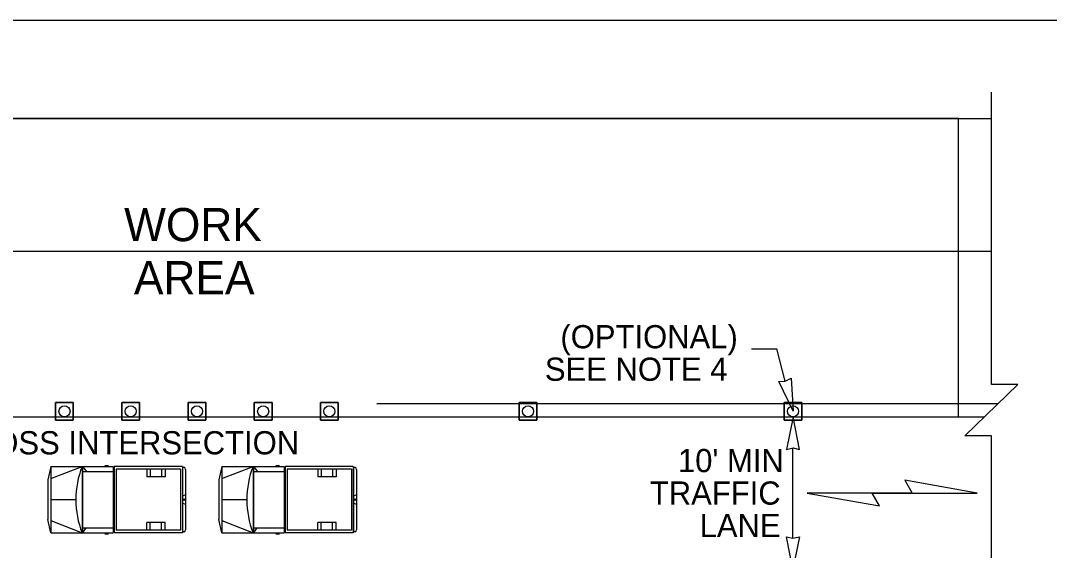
# Model space of a CAD drawing. Extents: x 99999.1 to 100095.7, y 99995 to 100010.7.
# Drawn here: x 100062.093 to 100065.2, y 100004.382 to 100005.98 of the extents above; entities that cross this region are included whole.
import ezdxf

# ---------------------------------------------------------------- set-up
doc = ezdxf.new("R2010")
doc.units = 0
for name, color, linetype in [('RD_ED_ShoulderPavedEdge', 7, 'Continuous'), ('RD_MK_LineDblYellowCenter', 7, 'Continuous'), ('RD_MK_LineEdgeWhite', 7, 'Continuous'), ('TR_WZ_MotoristVehicle', 7, 'Continuous'), ('TR_WZ_TrafficCone', 7, 'Continuous'), ('TR_WZ_WorkAreaLabel', 7, 'Continuous'), ('TR_WZ_WorkZoneDetails', 7, 'Continuous'), ('TR_WZ_WorkZoneTextCurrent', 7, 'Continuous')]:
    doc.layers.add(name, color=color, linetype=linetype)

msp = doc.modelspace()

# ---------------------------------------------------------------- linework, layer by layer
at = {"layer": 'RD_ED_ShoulderPavedEdge'}
msp.add_line((100060.225, 100005.6849), (100065.025, 100005.6849), dxfattribs=at)
at = {"layer": 'RD_MK_LineDblYellowCenter'}
for p, q in [((100063.1688, 100004.8249), (100065.0457, 100004.8249)), ((100063.1688, 100004.7849), (100065.0043, 100004.7849))]:
    msp.add_line(p, q, dxfattribs=at)
at = {"layer": 'RD_MK_LineEdgeWhite'}
msp.add_line((100060.225, 100005.2849), (100065.025, 100005.2849), dxfattribs=at)
at = {"layer": 'TR_WZ_MotoristVehicle'}
for p, q in [((100062.1843, 100004.6349), (100062.175, 100004.5946)), ((100062.1843, 100004.6349), (100062.1843, 100004.4349)), ((100062.1843, 100004.6349), (100062.3732, 100004.6349)), ((100062.1843, 100004.5983), (100062.2787, 100004.6349)), ((100062.2787, 100004.6349), (100062.2787, 100004.4349)), ((100062.2804, 100004.6349), (100062.2804, 100004.4349)), ((100062.2804, 100004.6349), (100062.2925, 100004.6194)), ((100062.3474, 100004.6377), (100062.3587, 100004.6377)), ((100062.3732, 100004.6349), (100062.3732, 100004.4349)), ((100062.5816, 100004.6349), (100062.3759, 100004.6349)), ((100062.3759, 100004.6349), (100062.3759, 100004.4349)), ((100062.5816, 100004.6349), (100062.5816, 100004.4349)), ((100062.5868, 100004.6316), (100062.5823, 100004.6316)), ((100062.5823, 100004.6316), (100062.5823, 100004.4382)), ((100062.7005, 100004.6349), (100062.6913, 100004.5946)), ((100062.7005, 100004.6349), (100062.7005, 100004.4349)), ((100062.7005, 100004.6349), (100062.8894, 100004.6349)), ((100062.7005, 100004.5983), (100062.795, 100004.6349)), ((100062.795, 100004.6349), (100062.795, 100004.4349)), ((100062.7967, 100004.6349), (100062.7967, 100004.4349)), ((100062.7967, 100004.6349), (100062.8087, 100004.6194)), ((100062.8637, 100004.6377), (100062.875, 100004.6377)), ((100062.8894, 100004.6349), (100062.8894, 100004.4349)), ((100063.0979, 100004.6349), (100062.8922, 100004.6349)), ((100062.8922, 100004.6349), (100062.8922, 100004.4349)), ((100063.0979, 100004.6349), (100063.0979, 100004.4349)), ((100063.1031, 100004.6316), (100063.0986, 100004.6316)), ((100063.0986, 100004.6316), (100063.0986, 100004.4382)), ((100062.2804, 100004.6194), (100062.3732, 100004.6194)), ((100062.5758, 100004.6269), (100062.3818, 100004.6269)), ((100062.3818, 100004.6269), (100062.3818, 100004.4429)), ((100062.4745, 100004.6269), (100062.4745, 100004.6039)), ((100062.5294, 100004.6039), (100062.4745, 100004.6039)), ((100062.4844, 100004.6269), (100062.4844, 100004.6039)), ((100062.5185, 100004.6269), (100062.5185, 100004.6039)), ((100062.5294, 100004.6269), (100062.5294, 100004.6039)), ((100062.5758, 100004.6269), (100062.5758, 100004.4429)), ((100062.5913, 100004.6255), (100062.5913, 100004.4443)), ((100062.7967, 100004.6194), (100062.8894, 100004.6194)), ((100063.0921, 100004.6269), (100062.898, 100004.6269)), ((100062.898, 100004.6269), (100062.898, 100004.4429)), ((100062.9908, 100004.6269), (100062.9908, 100004.6039)), ((100063.0457, 100004.6039), (100062.9908, 100004.6039)), ((100063.0007, 100004.6269), (100063.0007, 100004.6039)), ((100063.0347, 100004.6269), (100063.0347, 100004.6039)), ((100063.0457, 100004.6269), (100063.0457, 100004.6039)), ((100063.0921, 100004.6269), (100063.0921, 100004.4429)), ((100063.1075, 100004.6255), (100063.1075, 100004.4443)), ((100062.175, 100004.5946), (100062.175, 100004.4753)), ((100062.6913, 100004.5946), (100062.6913, 100004.4753)), ((100062.1843, 100004.5349), (100062.2602, 100004.5349)), ((100062.5913, 100004.549), (100062.5823, 100004.5453)), ((100062.5889, 100004.5349), (100062.5847, 100004.5349)), ((100062.5868, 100004.5377), (100062.5868, 100004.5321)), ((100062.7005, 100004.5349), (100062.7764, 100004.5349)), ((100063.1075, 100004.549), (100063.0986, 100004.5453)), ((100063.1051, 100004.5349), (100063.101, 100004.5349)), ((100063.1031, 100004.5377), (100063.1031, 100004.5321)), ((100062.5913, 100004.5208), (100062.5823, 100004.5246)), ((100063.1075, 100004.5208), (100063.0986, 100004.5246)), ((100062.1843, 100004.4349), (100062.175, 100004.4753)), ((100062.7005, 100004.4349), (100062.6913, 100004.4753)), ((100062.1843, 100004.4716), (100062.2787, 100004.4349)), ((100062.2804, 100004.4504), (100062.3732, 100004.4504)), ((100062.2904, 100004.4504), (100062.2804, 100004.4349)), ((100062.5758, 100004.4429), (100062.3818, 100004.4429)), ((100062.4745, 100004.4429), (100062.4745, 100004.4659)), ((100062.5294, 100004.4659), (100062.4745, 100004.4659)), ((100062.4844, 100004.4429), (100062.4844, 100004.4659)), ((100062.5185, 100004.4429), (100062.5185, 100004.4659)), ((100062.5294, 100004.4429), (100062.5294, 100004.4659)), ((100062.7005, 100004.4716), (100062.795, 100004.4349)), ((100062.7967, 100004.4504), (100062.8894, 100004.4504)), ((100062.8067, 100004.4504), (100062.7967, 100004.4349)), ((100063.0921, 100004.4429), (100062.898, 100004.4429)), ((100062.9908, 100004.4429), (100062.9908, 100004.4659)), ((100063.0457, 100004.4659), (100062.9908, 100004.4659)), ((100063.0007, 100004.4429), (100063.0007, 100004.4659)), ((100063.0347, 100004.4429), (100063.0347, 100004.4659)), ((100063.0457, 100004.4429), (100063.0457, 100004.4659)), ((100062.1843, 100004.4349), (100062.3732, 100004.4349)), ((100062.3474, 100004.4321), (100062.3587, 100004.4321)), ((100062.5816, 100004.4349), (100062.3759, 100004.4349)), ((100062.5868, 100004.4382), (100062.5823, 100004.4382)), ((100062.7005, 100004.4349), (100062.8894, 100004.4349)), ((100062.8637, 100004.4321), (100062.875, 100004.4321)), ((100063.0979, 100004.4349), (100062.8922, 100004.4349)), ((100063.1031, 100004.4382), (100063.0986, 100004.4382))]:
    msp.add_line(p, q, dxfattribs=at)
for centre, major_axis, start_param, end_param in [((100062.4137, 100004.5349), (0, -0.2099), 4.215667, 5.208926), ((100062.5868, 100004.6255), (0, 0.0061), 4.712389, 6.283185), ((100062.93, 100004.5349), (0, -0.2099), 4.215667, 5.208926), ((100063.1031, 100004.6255), (0, 0.0061), 4.712389, 6.283185), ((100062.5868, 100004.4443), (0, -0.0061), 0, 1.570796), ((100063.1031, 100004.4443), (0, -0.0061), 0, 1.570796)]:
    msp.add_ellipse(centre, major_axis=major_axis, ratio=0.73155, start_param=start_param, end_param=end_param, dxfattribs=at)
for centre in [(100062.5868, 100004.5349), (100063.1031, 100004.5349)]:
    msp.add_ellipse(centre, major_axis=(0, 0.00282), ratio=0.73155, dxfattribs=at)
at = {"layer": 'TR_WZ_TrafficCone'}
for points in [[(100062.199, 100004.8283), (100062.2524, 100004.8283), (100062.2524, 100004.7749), (100062.199, 100004.7749), (100062.199, 100004.8283)], [(100062.199, 100004.7749), (100062.2524, 100004.7749), (100062.2524, 100004.8283), (100062.199, 100004.8283), (100062.199, 100004.7749)], [(100062.399, 100004.8283), (100062.4524, 100004.8283), (100062.4524, 100004.7749), (100062.399, 100004.7749), (100062.399, 100004.8283)], [(100062.399, 100004.7749), (100062.4524, 100004.7749), (100062.4524, 100004.8283), (100062.399, 100004.8283), (100062.399, 100004.7749)], [(100062.599, 100004.8283), (100062.6524, 100004.8283), (100062.6524, 100004.7749), (100062.599, 100004.7749), (100062.599, 100004.8283)], [(100062.599, 100004.7749), (100062.6524, 100004.7749), (100062.6524, 100004.8283), (100062.599, 100004.8283), (100062.599, 100004.7749)], [(100062.799, 100004.8283), (100062.8524, 100004.8283), (100062.8524, 100004.7749), (100062.799, 100004.7749), (100062.799, 100004.8283)], [(100062.799, 100004.7749), (100062.8524, 100004.7749), (100062.8524, 100004.8283), (100062.799, 100004.8283), (100062.799, 100004.7749)], [(100062.999, 100004.8283), (100063.0524, 100004.8283), (100063.0524, 100004.7749), (100062.999, 100004.7749), (100062.999, 100004.8283)], [(100062.999, 100004.7749), (100063.0524, 100004.7749), (100063.0524, 100004.8283), (100062.999, 100004.8283), (100062.999, 100004.7749)], [(100063.599, 100004.8283), (100063.6524, 100004.8283), (100063.6524, 100004.7749), (100063.599, 100004.7749), (100063.599, 100004.8283)], [(100063.599, 100004.7749), (100063.6524, 100004.7749), (100063.6524, 100004.8283), (100063.599, 100004.8283), (100063.599, 100004.7749)], [(100064.399, 100004.8283), (100064.4524, 100004.8283), (100064.4524, 100004.7749), (100064.399, 100004.7749), (100064.399, 100004.8283)], [(100064.399, 100004.7749), (100064.4524, 100004.7749), (100064.4524, 100004.8283), (100064.399, 100004.8283), (100064.399, 100004.7749)]]:
    msp.add_lwpolyline(points, dxfattribs=at)
for centre in [(100062.2257, 100004.8016), (100062.4257, 100004.8016), (100062.6257, 100004.8016), (100062.8257, 100004.8016), (100063.0257, 100004.8016), (100063.6257, 100004.8016), (100064.4257, 100004.8016)]:
    msp.add_circle(centre, 0.0167, dxfattribs=at)
at = {"layer": 'TR_WZ_WorkZoneDetails'}
for p, q in [((100065.25, 100005.9805), (100060, 100005.9805)), ((100064.3007, 100004.9896), (100064.3769, 100004.9896)), ((100064.4022, 100004.8923), (100064.3769, 100004.9896)), ((100064.4256, 100004.4187), (100064.4256, 100004.6912)), ((100064.7856, 100004.5549), (100064.5445, 100004.5549)), ((100064.6651, 100004.5549), (100064.9062, 100004.5549))]:
    msp.add_line(p, q, dxfattribs=at)
msp.add_lwpolyline([(100065.025, 100003.8449), (100065.025, 100004.7275), (100064.945, 100004.7275), (100065.105, 100004.8824), (100065.025, 100004.8824), (100065.025, 100005.7649)], dxfattribs=at)
for points in [[(100060.325, 100005.6849), (100060.325, 100004.7849), (100064.925, 100004.7849), (100064.925, 100005.6849)], [(100064.4257, 100004.8016), (100064.3824, 100004.8919), (100064.4022, 100004.8923), (100064.4197, 100004.9016)], [(100064.4257, 100004.7849), (100064.4064, 100004.6866), (100064.4257, 100004.6912), (100064.445, 100004.6866)], [(100064.9821, 100004.5549), (100064.7633, 100004.5935), (100064.7856, 100004.5549)], [(100064.4685, 100004.5549), (100064.6873, 100004.5164), (100064.6651, 100004.5549)], [(100064.4256, 100004.3249), (100064.4064, 100004.4232), (100064.4256, 100004.4187), (100064.4449, 100004.4232)]]:
    msp.add_lwpolyline(points, close=True, dxfattribs=at)

# ---------------------------------------------------------------- texts
at = {"layer": 'TR_WZ_WorkAreaLabel'}
for s, p in [('WORK', (100062.4058, 100005.3149)), ('AREA', (100062.4354, 100005.1549))]:
    msp.add_text(s, height=0.1, dxfattribs=at).set_placement(p)
at = {"layer": 'TR_WZ_WorkZoneTextCurrent'}
for s, p in [('(OPTIONAL)', (100063.7233, 100004.9916)), ('SEE NOTE 4', (100063.6764, 100004.8936)), ("10' SPACING ACROSS INTERSECTION", (100061.2208, 100004.6716)), ("10' MIN", (100064.0783, 100004.6179)), ('TRAFFIC', (100063.9933, 100004.5199)), ('LANE', (100064.1437, 100004.4219))]:
    msp.add_text(s, height=0.07, dxfattribs=at).set_placement(p)

doc.saveas('drawing.dxf')
